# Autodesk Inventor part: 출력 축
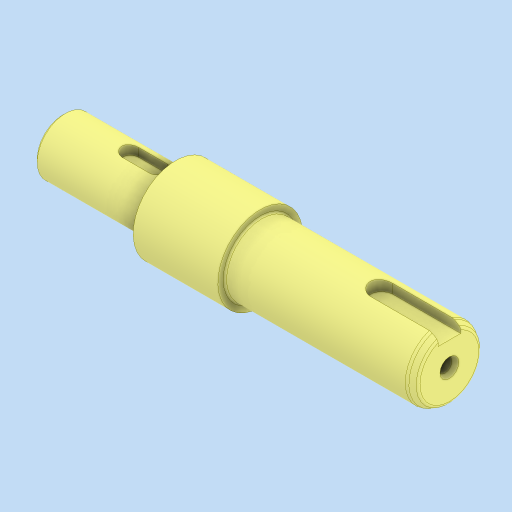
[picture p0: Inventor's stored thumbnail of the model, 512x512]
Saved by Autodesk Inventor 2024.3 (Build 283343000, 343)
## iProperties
Created: 2025-11
Part Number: 출력 축
Material: 강철, 탄소
Document SubType Name: Modeling
Designer: PC2-02
Density: 7.85 g/cm^3
Appearance: 기본값
Author: jhkim
Sending System: Autodesk Inventor 2026
Preprocessor: ST-DEVELOPER v20.1
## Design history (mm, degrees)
node "출력 축1"
node "솔리드2"
node "솔리드1"
